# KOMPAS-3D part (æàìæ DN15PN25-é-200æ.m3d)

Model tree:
1. Объединить компоненты:1  (labels: СЕНС DN15PN25-В-200С)

Referenced files in D:\Савин\!СЕНСОР\3D для заказчика\!Новый перечень\СЕНС\4. СЕНС-В-200С\DN15\: СЕНС DN15PN25-В-200С.a3d
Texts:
  СЕНС DN15PN25-В-200С
  ООО НПП Сенсор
